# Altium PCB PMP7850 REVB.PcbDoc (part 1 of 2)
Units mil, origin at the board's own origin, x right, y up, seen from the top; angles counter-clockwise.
Board outline 4000 x 3000 mil, 4 copper layers (Top Layer, MidLayer1, MidLayer2, Bottom Layer), stack 61.2 mil thick; 106 components, 51 nets, 290 pads, 278 vias.
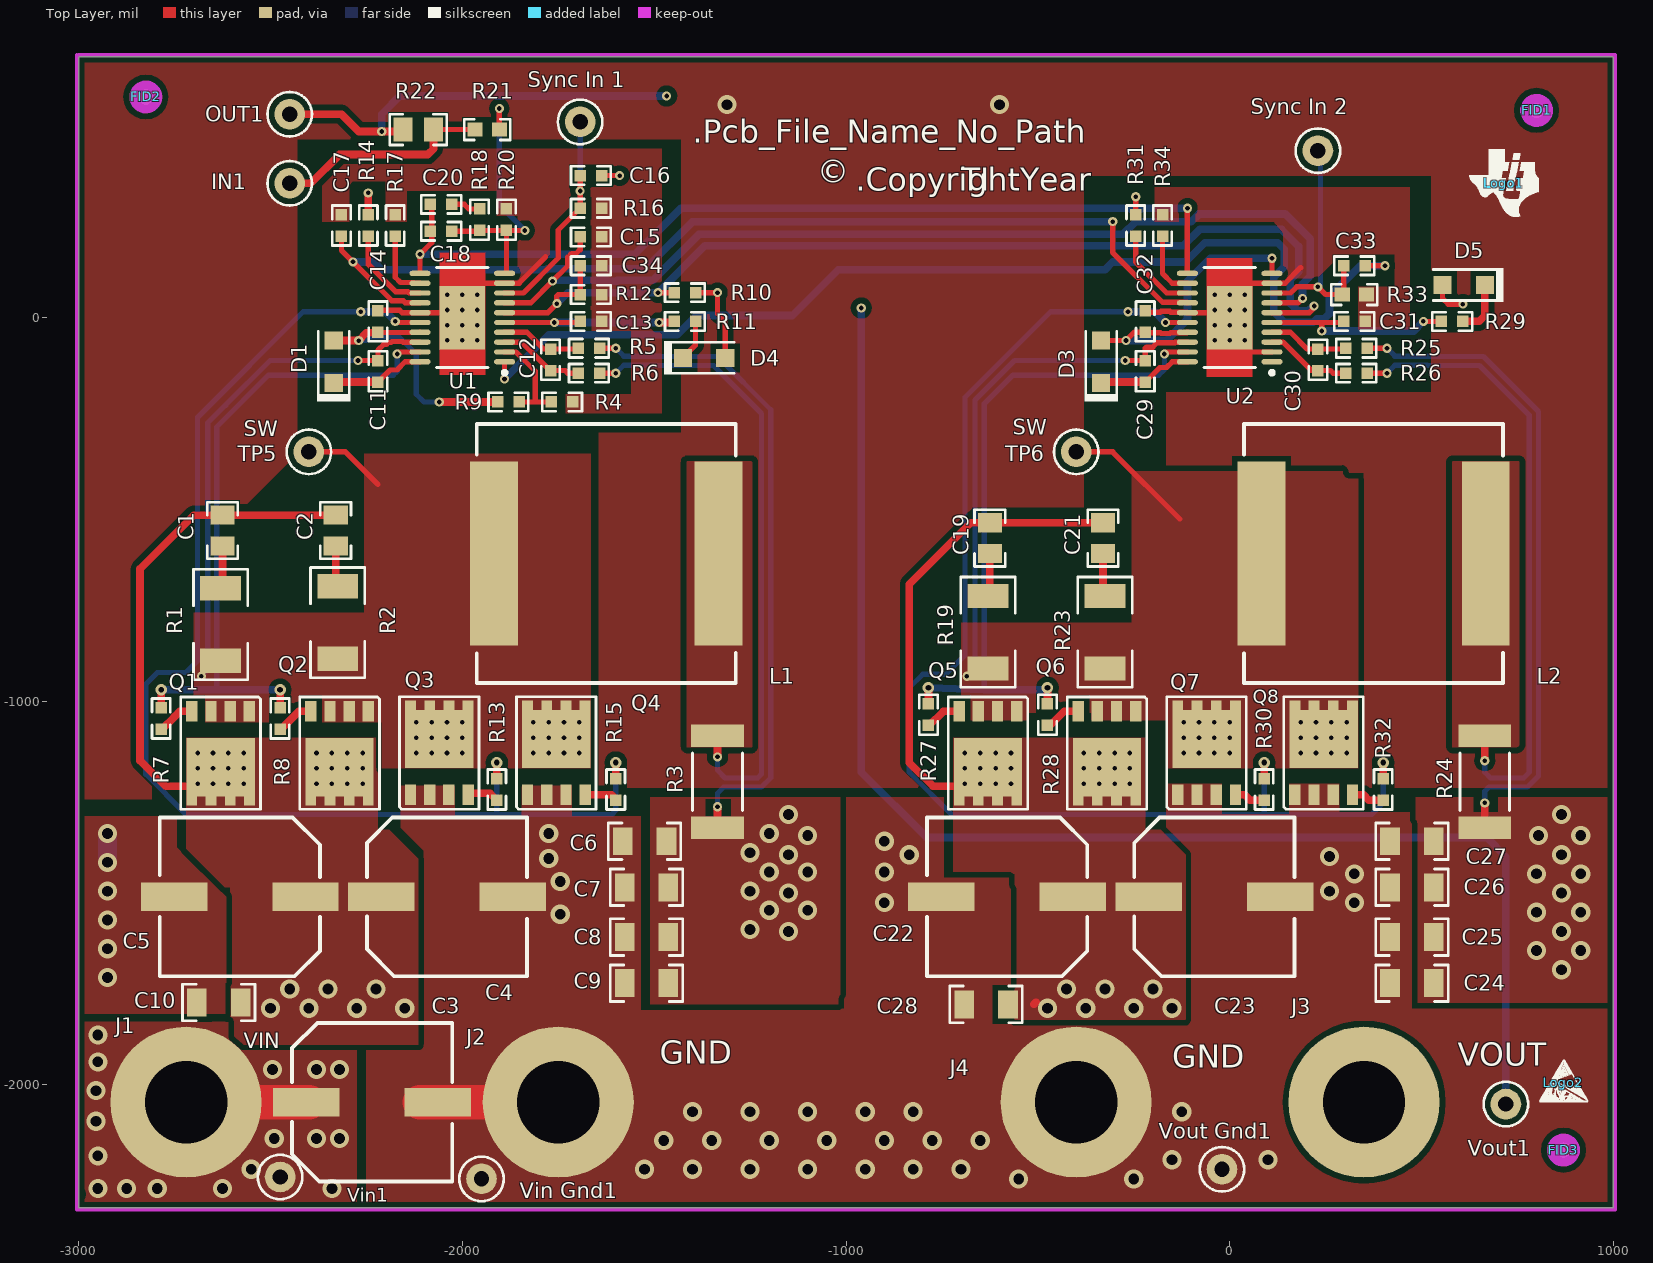
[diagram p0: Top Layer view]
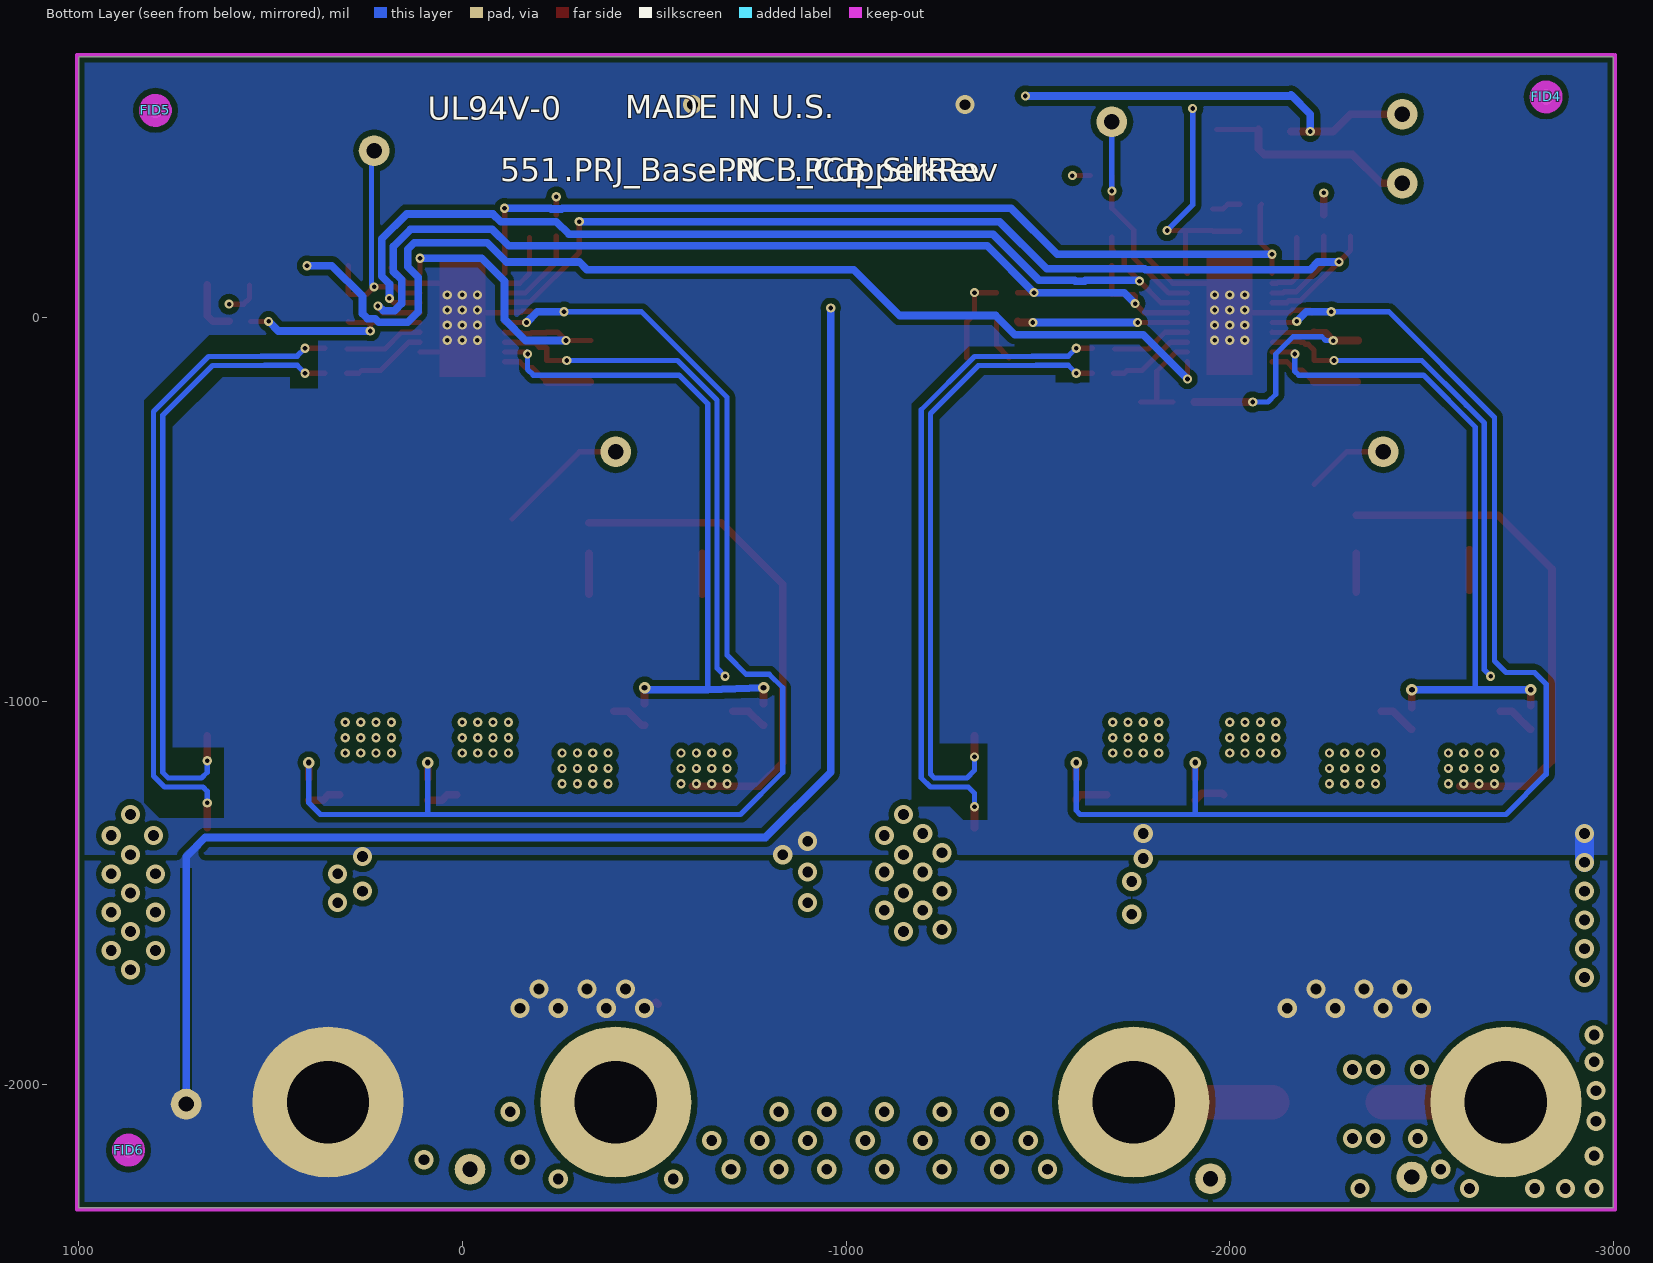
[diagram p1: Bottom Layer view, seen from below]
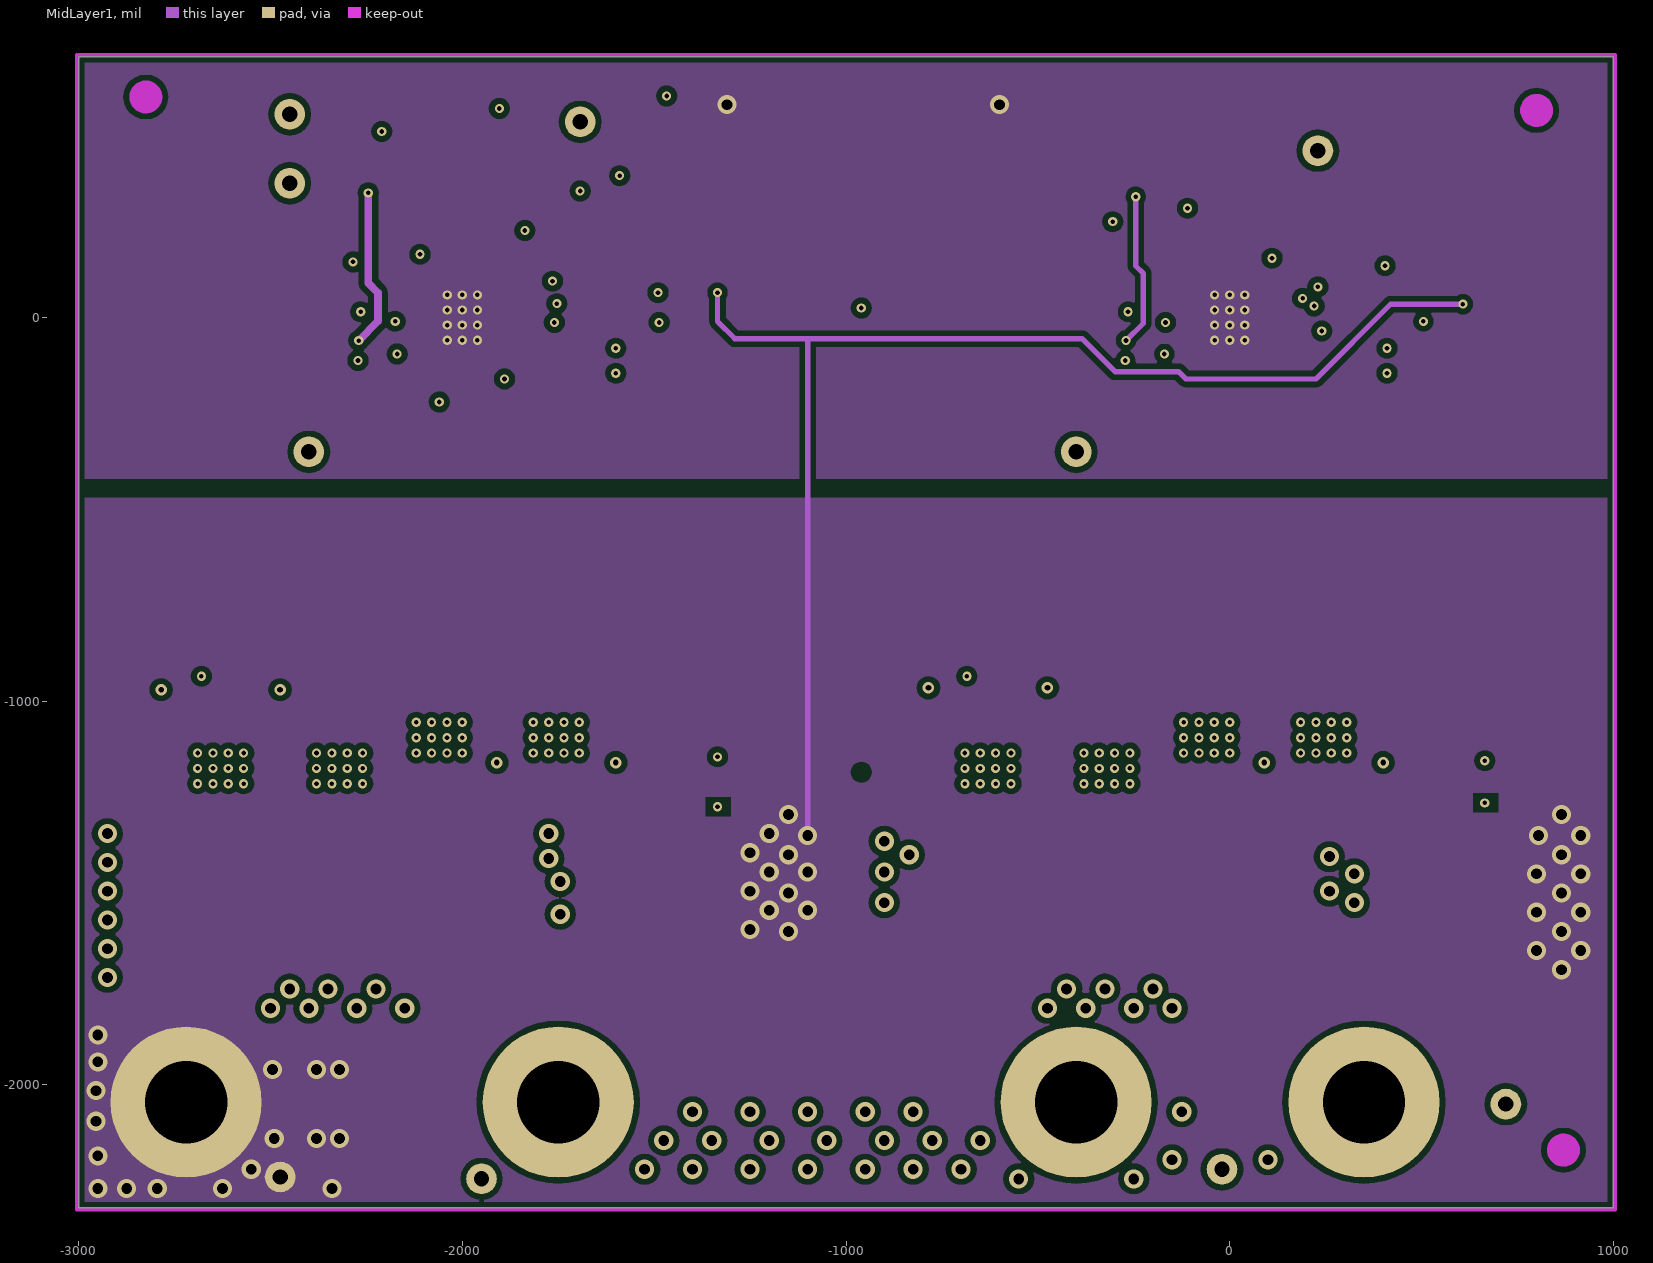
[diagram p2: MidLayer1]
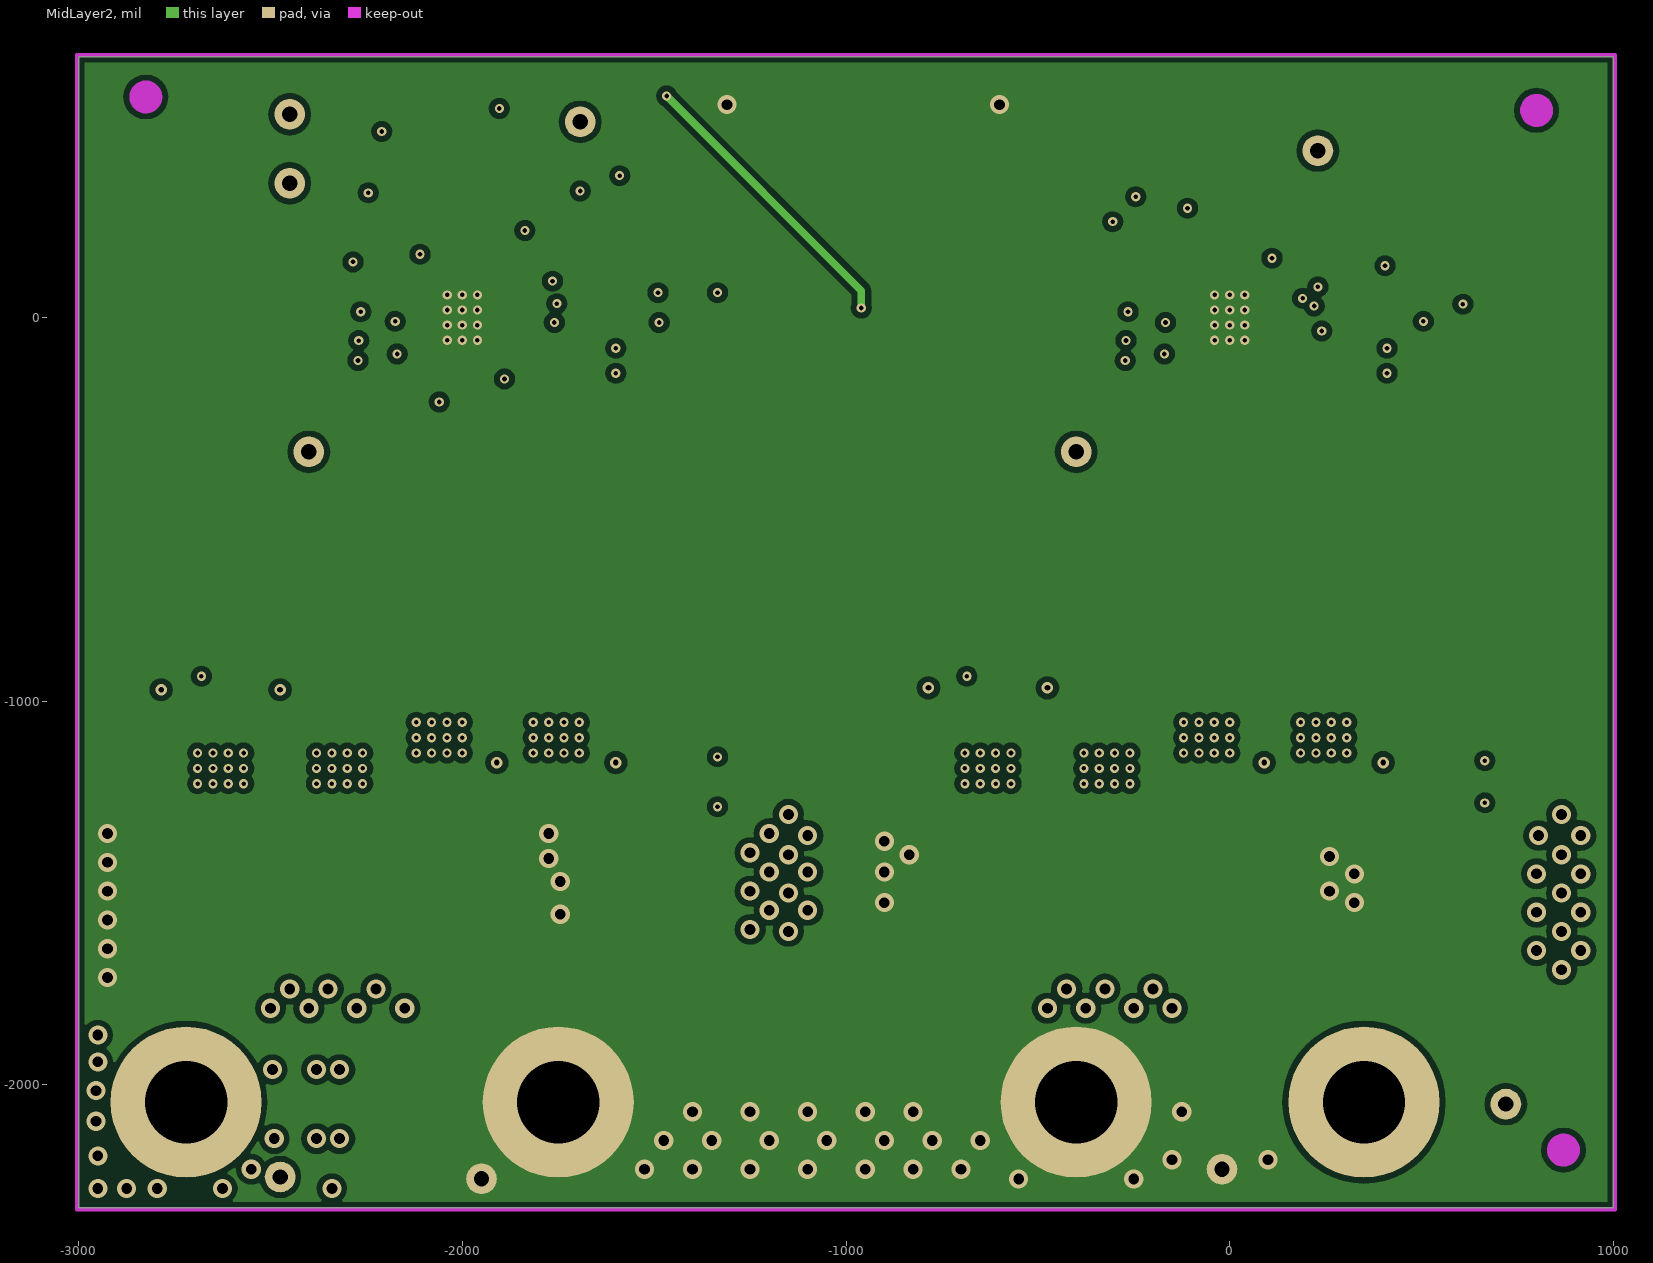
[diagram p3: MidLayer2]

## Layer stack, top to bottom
Top Solder: solder mask 0.4, Solder Resist, Dk 3.5
Top Layer: signal copper 1.4
Dielectric1: core 12.6, FR-4, Dk 4.8
MidLayer1: signal copper 0.7
Dielectric2: prepreg 31.8, FR-4, Dk 4.8
MidLayer2: signal copper 0.7
Dielectric3: core 12.6, FR-4, Dk 4.8
Bottom Layer: signal copper 1.4
Bottom Solder: solder mask 0.4, Solder Resist, Dk 3.5

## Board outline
-3000,-2320 -3000,680 1000,680 1000,-2320

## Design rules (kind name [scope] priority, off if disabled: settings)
AcuteAngle [All] p1: minimum=4.50000000000000E+0001 checktracksonly=FALSE
AssemblyTestPointUsage [All] p1: valid=2
Clearance Clearance_Polygons [IsRegion] p1: gap=15
Clearance Clearance_BoardEdge_MountingHoles [OnCopper and InComponentClass('Mounting Holes') vs IsKeepOut] p2: gap=40
Clearance Clearance_BoardEdge_Poly [OnCopper and InPoly vs IsKeepOut] p3: gap=25
Clearance Clearance_BoardEdge [OnCopper and Not InComponentClass('Logo') and not InComponentClass('FiducialMark') and not InRegion(1000,500,4000,800) vs IsKeepOut] p4: gap=75
Clearance Clearance_1 [All] p5: gap=10
ComponentClearance ComponentClearance_Logo [InComponentClass(Logo)] p1: gap=50 collisioncheckmode=3 verticalgap=10 showdistances=FALSE
ComponentClearance ComponentClearance_ScrewToNut [(HasFootprint('NY PMS 440 0025 PH')) vs (HasFootprint('Keystone_1902C'))] p2: gap=5 collisioncheckmode=3 verticalgap=10 showdistances=FALSE
ComponentClearance ComponentClearance_MountingHoles [InComponentClass('Mounting Holes')] p3: gap=250 collisioncheckmode=3 verticalgap=100000 showdistances=FALSE
ComponentClearance ComponentClearance_SmallPassives [HasFootprint('0201*') or HasFootprint('0402*') or HasFootprint('0508') or HasFootprint('0603*') or HasFootprint('0612') or HasFootprint('0805*') or HasFootprint('0815*') or HasFootprint('0830*') or HasFootprint('1206*') or HasFootprint('1210*') or HasFootprint('1808*') or HasFootprint('1812*') or HasFootprint('1825*') or HasFootprint('2010*') or HasFootprint('2220*') or HasFootprint('2225*') or HasFootprint('2512*') or HasFootprint('2728*') or HasFootprint('3518*') vs HasFootprint('0201*') or HasFootprint('0402*') or HasFootprint('0508') or HasFootprint('0603*') or HasFootprint('0612') or HasFootprint('0805*') or HasFootprint('0815*') or HasFootprint('0830*') or HasFootprint('1206*') or HasFootprint('1210*') or HasFootprint('1808*') or HasFootprint('1812*') or HasFootprint('1825*') or HasFootprint('2010*') or HasFootprint('2220*') or HasFootprint('2225*') or HasFootprint('2512*') or HasFootprint('2728*') or HasFootprint('3518*')] p4: gap=20 collisioncheckmode=3 verticalgap=10 showdistances=FALSE
ComponentClearance ComponentClearance_THtoSMT [IsThruComponent vs IsSMTComponent] p5: gap=100 collisioncheckmode=3 verticalgap=100000 showdistances=FALSE
ComponentClearance ComponentClearance_THtoTH [IsThruComponent vs IsThruComponent] p6: gap=118.11 collisioncheckmode=3 verticalgap=100000 showdistances=FALSE
ComponentClearance [All] p7: gap=40 collisioncheckmode=3 verticalgap=10 showdistances=FALSE
DiffPairsRouting [All] p1: maxlimit=100 minlimit=10 mostfreqgap=10 toplayer_minwidth=15 toplayer_maxwidth=15 toplayer_prefwidth=15 midlayer1_minwidth=15 midlayer1_maxwidth=15 midlayer1_prefwidth=15 midlayer2_minwidth=15 midlayer2_maxwidth=15 midlayer2_prefwidth=15 bottomlayer_minwidth=15 bottomlayer_maxwidth=15 bottomlayer_prefwidth=15 maxuncoupledlength=1000
FabricationTestPointUsage TestPointUsage [All] p1: valid=2 allowmultiple=FALSE
FabricationTestpoint Testpoint [All] p1: side=3 testpointundercomponent=TRUE minsize=40 maxsize=100 preferedsize=60 minholesize=0 maxholesize=40 preferedholesize=32 testpointgrid=1 allowsidetop=TRUE allowsidebottom=TRUE usegrid=TRUE gridtolerance=0.01
FanoutControl Fanout_LCC [IsLCC] p1: bgadir=Out bgaviamode=Centered fanoutstyle=Auto fanoutdirection=Alternating viagrid=1 // Fanout_LCC (Default Rule)
FanoutControl Fanout_BGA [IsBGA] p2: bgadir=Out bgaviamode=Centered fanoutstyle=Auto fanoutdirection=Alternating viagrid=1 // Fanout_BGA (Default Rule)
FanoutControl Fanout_Default [All] p4: bgadir=Out bgaviamode=Centered fanoutstyle=Auto fanoutdirection=Alternating viagrid=1 // Fanout_Default (Default Rule)
FanoutControl Fanout_Small [(CompPinCount < 5)] p5: bgadir=Out bgaviamode=Centered fanoutstyle=Auto fanoutdirection=OutThenIn viagrid=1 // Fanout_Small (Default Rule)
HoleSize [All] p1: absolutevalues=TRUE maxlimit=251 minlimit=8 maxpercent=80.000 minpercent=20.000
MinimumAnnularRing [All] p1: minimumring=6
MinimumSolderMaskSliver MinimumSolderMaskSliver_Logo [InComponentClass('Logo') vs InComponentClass('Logo')] p1: minsoldermaskwidth=0.7
MinimumSolderMaskSliver [All] p2: minsoldermaskwidth=4
PlaneConnect [All] p1: planeconnectstyle=Relief reliefexpansion=10 reliefentries=4 reliefconductorwidth=10 reliefairgap=10
PolygonConnect [All] p1: connectstyle=Direct reliefconductorwidth=10 reliefentries=4 polygonreliefangle="90 Angle" airgapwidth=10
RoomDefinition "PMP7850 2 phase design Rev 3 Schematic" [InComponentClass('PMP7850 2 phase design Rev 3 Schematic')] p1 off: confinementstyle=ConfineIn formatcopy=TRUE lockcomponents=FALSE outline -3692,-3854 -1692,-3854 -1692,-2854 -3692,-2854
RoutingVias [All] p1: holewidth=16 width=34 viastyle="Through Hole" minholewidth=8 minwidth=26 maxholewidth=40 maxwidth=65
SMDToCorner [All] p1: distance=30000
SilkToSilkClearance [All] p1: silktosilkclearance=5
SilkToSolderMaskClearance SilkscreenOverComponentPads [IsPad] p1: minsilkscreentomaskgap=5 clearancetoexposedcopper=TRUE
SolderMaskExpansion [All] p1: expansion=3
UnpouredPolygon [All] p1: allowunpoured=FALSE
Width [All] p1: maxlimit=100 minlimit=6 preferedwidth=10 checkconnectedcopper=TRUE
15 further rules are at their usual default settings.

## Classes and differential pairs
component class "PMP7850 2 phase design Rev 3 Schematic": C1 C2 C3 C4 C5 C6 C7 C8 C9 C10 C11 C12 C13 C14 C15 C16 C17 C18 C19 C20 C21 C22 C23 C24 C25 C26 C27 C28 C29 C30 C31 C32 C33 C34 D1 D3 D4 D5 IN1 J1 J2 J3 J4 L1 L2 OUT1 Q1 Q2 Q3 Q4 Q5 Q6 Q7 Q8 R1 R2 R3 R4 R5 R6 R7 R8 R9 R10 R11 R12 R13 R14 R15 R16 R17 R18 R19 R20 R21 R22 R23 R24 R25 R26 R27 R28 R29 R30 R31 R32 R33 R34 "Sync In 1" "Sync In 2" TP5 TP6 U1 U2 Vin1 "Vin Gnd1" Vout1 "Vout Gnd1"
component class FiducialMark: FID1 FID2 FID3 FID4 FID5 FID6
component class 870xxxxxx_Hardware_ANSI-B: FID1 FID2 FID3 FID4 FID5 FID6 Logo1 Logo2
component class Logo: Logo1
differential pair SW1: +SW1_P -SW1_N
differential pair SW2: +SW2_P -SW2_N

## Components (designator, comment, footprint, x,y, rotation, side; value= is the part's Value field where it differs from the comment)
C1 "GRM2165C2A471JA01D" 0805_HV -2625,-555 r270 top
C2 "GRM2165C2A471JA01D" 0805_HV -2330,-555 r270 top
C3 "10SVPS330M" SVPS_F8 -2235,-2045 r0 top
C4 "16SVP180MX" SVP_F8 -2040,-1510 r0 top
C5 "16SVP180MX" SVP_F8 -2580,-1510 r180 top
C6 "C3216X5R1C106M" 1206 -1525,-1365 r180 top
C7 "C3216X5R1C106M" 1206 -1520,-1485 r180 top
C8 "C3216X5R1C106M" 1206 -1520,-1615 r180 top
C9 "C3216X5R1C106M" 1206 -1520,-1735 r180 top
C10 "C3216X5R1C106M" 1206 -2635,-1785 r180 top
C11 "GRM188R71E474KA12D" 0603_HV -2220,-140 r270 top
C12 "GRM1885C1H101JA01D" 0603_HV -1770,-110 r90 top
C13 "GRM188R71E474KA12D" 0603_HV -1665,-10 r0 top
C14 "GRM188R71E105KA12D" 0603_HV -2220,-10 r90 top
C15 "GRM188R71E104KA01D" 0603_HV -1665,210 r0 top
C16 "GRM1885C1H101JA01D" 0603_HV -1665,370 r180 top
C17 "GRM188R71E473KA01D" 0603_HV -2315,240 r90 top
C18 "GRM1885C1H101JA01D" 0603_HV -2055,225 r180 top
C19 "GRM2165C2A471JA01D" 0805_HV -625,-575 r270 top
C20 "C0603C223K3RACTU" 0603_HV -2055,295 r180 top
C21 "GRM2165C2A471JA01D" 0805_HV -330,-575 r270 top
C22 "16SVP180MX" SVP_F8 -580,-1510 r180 top
C23 "16SVP180MX" SVP_F8 -40,-1510 r0 top
C24 "C3216X5R1C106M" 1206 475,-1735 r180 top
C25 "C3216X5R1C106M" 1206 475,-1615 r180 top
C26 "C3216X5R1C106M" 1206 475,-1485 r180 top
C27 "C3216X5R1C106M" 1206 475,-1365 r180 top
C28 "C3216X5R1C106M" 1206 -635,-1790 r180 top
C29 "GRM188R71E474KA12D" 0603_HV -220,-140 r270 top
C30 "GRM1885C1H101JA01D" 0603_HV 230,-110 r90 top
C31 "GRM188R71E474KA12D" 0603_HV 325,-10 r0 top
C32 "GRM188R71E105KA12D" 0603_HV -220,-10 r90 top
C33 "GRM1885C1H101JA01D" 0603_HV 325,135 r180 top
C34 "GRM188R71C103KA01D" 0603_HV -1665,135 r0 top
D1 "PMEG6010CEH,115" SOD-123F -2335,-115 r90 top
D3 "PMEG6010CEH,115" SOD-123F -335,-115 r90 top
D4 "PMEG6010CEH,115" SOD-123F -1370,-105 r0 top
D5 "PMEG6010CEH,115" SOD-123F 610,85 r180 top
FID1 "Fiducial" Fiducial10-20 800,540 r0 top
FID2 "Fiducial" Fiducial10-20 -2825,575 r0 top
FID3 "Fiducial" Fiducial10-20 870,-2170 r0 top
FID4 "Fiducial" Fiducial10-20 -2825,575 r270 bottom
FID5 "Fiducial" Fiducial10-20 800,540 r270 bottom
FID6 "Fiducial" Fiducial10-20 870,-2170 r270 bottom
IN1 "5002" Keystone5002 -2450,350 r0 top
J1 "575-4" Keystone_575-4 -2720,-2045 r0 top
J2 "575-4" Keystone_575-4 -1750,-2045 r0 top
J3 "575-4" Keystone_575-4 350,-2045 r0 top
J4 "575-4" Keystone_575-4 -400,-2045 r0 top
L1 "IHLP6767GZER3R3MA1" IHLP6767GZ -1625,-615 r180 top
L2 "IHLP6767GZER3R3MA1" IHLP6767GZ 375,-615 r180 top
Logo1 "Texas Instruments" TI_Symbol_Overlay_Small 715,350 r0 top
Logo2 "ESD Susceptible" ESD_Overlay_Small 870,-1995 r0 top
OUT1 "5002" Keystone5002 -2450,530 r0 top
Q1 "CSD16415Q5" "Q5A WITH VIAS" -2630,-1135 r270 top
Q2 "CSD16415Q5" "Q5A WITH VIAS" -2320,-1135 r270 top
Q3 "CSD16415Q5" "Q5A WITH VIAS" -2060,-1135 r90 top
Q4 "CSD16415Q5" "Q5A WITH VIAS" -1755,-1135 r90 top
Q5 "CSD16415Q5" "Q5A WITH VIAS" -630,-1135 r270 top
Q6 "CSD16415Q5" "Q5A WITH VIAS" -320,-1135 r270 top
Q7 "CSD16415Q5" "Q5A WITH VIAS" -60,-1135 r90 top
Q8 "CSD16415Q5" "Q5A WITH VIAS" 245,-1135 r90 top
R1 "ERJ-12ZYJ7R5U" 2010M -2630,-800 r270 top
R2 "ERJ-12ZYJ7R5U" 2010M -2325,-795 r270 top
R3 "ERJ-M1WTF1M5U" 2512M -1335,-1210 r90 top
R4 "ERJ-3GEY0R00V" 0603_HV -1740,-220 r180 top
R5 "CRCW0603100RFKEA" 0603_HV -1670,-80 r0 top
R6 "CRCW0603100RFKEA" 0603_HV -1670,-145 r0 top
R7 "ERJ-3GEY0R00V" 0603_HV -2785,-1045 r90 top
R8 "ERJ-3GEY0R00V" 0603_HV -2475,-1045 r90 top
R9 "CRCW0603158KFKEA" 0603_HV -1880,-220 r180 top
R10 "CRCW060349K9FKEA" 0603_HV -1420,65 r0 top
R11 "CRCW06033R30JNEA" 0603_HV -1420,-10 r0 top
R12 "RC0603FR-0715KL" 0603_HV -1665,60 r180 top
R13 "ERJ-3GEY0R00V" 0603_HV -1910,-1230 r90 top
R14 "ERJ-3GEY0R00V" 0603_HV -2245,240 r90 top
R15 "ERJ-3GEY0R00V" 0603_HV -1600,-1230 r90 top
R16 "CRCW060320K0FKEA" 0603_HV -1665,285 r180 top
R17 "RC0603FR-0739KL" 0603_HV -2175,240 r270 top
R18 "CRCW060315K0FKEA" 0603_HV -1955,255 r90 top
R19 "ERJ-12ZYJ7R5U" 2010M -630,-820 r270 top
R20 "CRCW06032K67FKEA" 0603_HV -1885,255 r90 top
R21 "CRCW060323K2FKEA" 0603 -1935,490 r180 top
R22 "CRCW0805604RFKEA" 0805_HV -2115,490 r0 top
R23 "ERJ-12ZYJ7R5U" 2010M -325,-820 r270 top
R24 "ERJ-M1WTF1M5U" 2512M 665,-1210 r90 top
R25 "CRCW0603100RFKEA" 0603_HV 330,-80 r0 top
R26 "CRCW0603100RFKEA" 0603_HV 330,-145 r0 top
R27 "ERJ-3GEY0R00V" 0603_HV -785,-1035 r90 top
R28 "ERJ-3GEY0R00V" 0603_HV -475,-1035 r90 top
R29 "CRCW06033R30JNEA" 0603_HV 580,-10 r0 top
R30 "ERJ-3GEY0R00V" 0603_HV 90,-1230 r90 top
R31 "ERJ-3GEY0R00V" 0603_HV -245,240 r90 top
R32 "ERJ-3GEY0R00V" 0603_HV 400,-1230 r90 top
R33 "CRCW060320K0FKEA" 0603 325,60 r180 top
R34 "RC0603FR-0739KL" 0603_HV -175,240 r270 top
"Sync In 1" "5002" Keystone5002 -1693,510 r0 top
"Sync In 2" "5002" Keystone5002 230,435 r90 top
TP5 "5002" Keystone5002 -2400,-350 r0 top
TP6 "5002" Keystone5002 -400,-350 r0 top
U1 "LM5122MH" "MXA20A_L - 10milVia" -2000,0 r180 top
U2 "LM5122MH" "MXA20A_L - 10milVia" 0,0 r180 top
Vin1 "5000" Keystone5000 -2475,-2240 r0 top
"Vin Gnd1" "5001" Keystone5001 -1950,-2245 r90 top
Vout1 "5000" Keystone5000 720,-2050 r90 top
"Vout Gnd1" "5001" Keystone5001 -20,-2220 r90 top

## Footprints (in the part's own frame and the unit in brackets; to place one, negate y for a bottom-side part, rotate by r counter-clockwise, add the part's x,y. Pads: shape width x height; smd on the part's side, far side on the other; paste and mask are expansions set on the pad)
0603 [mm] "0603 from SM-752 data"
  rect 1x0.95 smd: 1(-0.8,0) 2(0.8,0)
  silkscreen extent -1.52,-0.69 1.52,0.69, body extent -0.87,-0.47 0.87,0.47, height 0.85
0603_HV [mil] "Ernesto recommended land pattern.  26 mil between pads."
  rect 30x30 smd: 1(-28,0) 2(28,0)
  silkscreen extent -52,-24 52,24, body extent -34,-19 34,19, height 33
0805_HV [mil] "0805 with 30mil clearance between pads"
  rect 50x63 smd: 1(-40,0) 2(40,0)
  silkscreen extent -74,-40 74,40, body extent -43,-29 43,29, height 43
1206 [mm] "1206 from SM-752 data"
  rect 1.3x1.85 smd: 1(-1.45,0) 2(1.45,0)
  silkscreen extent -2.4,-1.21 2.4,1.21, body extent -1.7,-0.9 1.7,0.9, height 1.35
2010M [mm]
  rect 1.6x2.7 smd: 1(-2.4,0) 2(2.4,0)
  silkscreen extent -3.65,-1.8 3.65,1.8, body extent -2.73,-1.45 2.73,1.45, height 1.66
2512M [mm] "Chip Resistor, Body 6.3x3.2mm, IPC Low Density"
  rect 1.5x3.5 smd: 1(-3.05,0) 2(3.05,0)
  silkscreen extent -1.9,-1.65 1.9,1.65, body extent -3.22,-1.67 3.22,1.67, height 0.71
ESD_Overlay_Small [mil]
  silkscreen extent -62,-48 64,61
Fiducial10-20 [mm]
  round 1 smd paste-0.5 mask+0.5: 1(0,0)
  Keep-Out Layer circle w1.178: c0,0 r0.5
IHLP6767GZ [mm] "IHLP6767GZ VISHAY DALE INDUCTOR"
  rect 3.175x12.19 smd: 1(-7.428,0) 2(7.428,0)
  silkscreen extent -8.57,-8.57 8.57,8.57, body extent -8.62,-8.6 8.67,8.67, height 7
Keystone5000 [mil] "For Keystone 500x miniature loop terminals"
  round 80 hole 40: 1(0,0)
  silkscreen extent -58,-58 58,58, body extent -49,-49 49,49, height 182
Keystone5001 [mil] "For Keystone 500x miniature loop terminals"
  round 80 hole 40: 1(0,0)
  silkscreen extent -58,-58 58,58, body extent -49,-49 49,49, height 182
Keystone5002 [mil] "For Keystone 500x miniature loop terminals"
  round 80 hole 40: 1(0,0)
  silkscreen extent -58,-58 58,58, body extent -49,-49 49,49, height 182
Keystone_575-4 [mm] "Banana Jack"
  round 10 hole 5.45: 1(0,0)
  body extent -3.95,-3.95 3.92,3.93, height 2.36
"MXA20A_L - 10milVia" [mm] "TSOP, 20-Leads, Body 6.5x4.4mm, Pitch 0.65mm, Exposed Pad, IPC High Density"
  oval 1.4x0.35 smd: 1(-2.8,2.925) 2(-2.8,2.275) 3(-2.8,1.625) 4(-2.8,0.975) 5(-2.8,0.325) 6(-2.8,-0.325) 7(-2.8,-0.975) 8(-2.8,-1.625) 9(-2.8,-2.275) 10(-2.8,-2.925) 11(2.8,-2.925) 12(2.8,-2.275) 13(2.8,-1.625) 14(2.8,-0.975) 15(2.8,-0.325) 16(2.8,0.325) 17(2.8,0.975) 18(2.8,1.625) 19(2.8,2.275) 20(2.8,2.925)
  rect 3x4.2 smd: 21(0,0)
  silkscreen extent -2.93,-3.3 1.7,3.77, body extent -2.25,-3.3 2.25,3.3, height 1.1
"Q5A WITH VIAS" [mm] "TI 15A WITH VIAS"
  round 0.3 on Top Overlay: 0(-2.766,3.087)
  rect 1.372x0.75 smd paste-0.1 mask+0.051: 1(-2.77,1.905) 2(-2.77,0.635) 3(-2.77,-0.635) 4(-2.77,-1.905)
  rect 0.675x0.71 smd paste-0.1 mask+0.051: 5(3.134,-1.905) 6(3.134,-0.635) 7(3.134,0.635) 8(3.134,1.905)
  rect 3.85x4.52 smd paste-2.2 mask+0.051: 9(0.939,0)
  silkscreen extent -3.71,-2.63 3.72,2.64, body extent -3.05,-2.5 3.05,2.5, height 1.11
SOD-123F [mm] "NXP recommended land pattern"
  rect 1.2x1.2 smd paste-0.05: 1(-1.4,0) 2(1.4,0)
  silkscreen extent -2.64,-1.12 2.01,1.12, body extent -1.8,-0.85 1.8,0.85, height 1.2
SVP_F8 [mm] "SANYO SVP_F8"
  rect 4.4x1.9 smd: 1(-4.35,0) 2(4.35,0)
  silkscreen extent -5.3,-5.25 5.3,5.25, body extent -5.25,-5.23 5.33,5.2, height 8
SVPS_F8 [mm] "SANYO SVPS_F8"
  rect 4.4x1.9 smd: 1(-4.35,0) 2(4.35,0)
  silkscreen extent -5.3,-5.25 5.3,5.25, body extent -5.25,-5.23 5.33,5.2, height 8
TI_Symbol_Overlay_Small [mil]
  silkscreen extent -90,-88 91,88

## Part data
C1 C2 C19 C21: "CAP, CERM, 470pF, 100V, +/-5%, C0G/NP0, 0805"
C3: "CAP, AL, 330uF, 10V, +/-20%, SMD"
C4 C5 C22 C23: "CAP, AL, 180uF, 16V, +/-20%, SMD"
C6 C7 C8 C9 C10 C24 C25 C26 C27 C28: "CAP, CERM, 10uF, 16V, +/-20%, X5R, 1206"
C11 C13 C29 C31: "CAP, CERM, 0.47uF, 25V, +/-10%, X7R, 0603"
C12 C16 C18 C30 C33: "CAP, CERM, 100pF, 50V, +/-5%, C0G/NP0, 0603"
C14 C32: "CAP, CERM, 1uF, 25V, +/-10%, X7R, 0603"
C15: "CAP, CERM, 0.1uF, 25V, +/-10%, X7R, 0603"
C17: "CAP, CERM, 0.047uF, 25V, +/-10%, X7R, 0603"
C20: "CAP, CERM, 0.022uF, 25V, +/-10%, X7R, 0603"
C34: "CAP, CERM, 0.01uF, 16V, +/-10%, X7R, 0603"
D1 D3 D4 D5: "Diode, Schottky, 60V, 1A, SOD-123F"
FID1 FID2 FID3 FID4 FID5 FID6: "Fiducial mark.  There is nothing to buy or mount."
IN1 OUT1 "Sync In 1" "Sync In 2" TP5 TP6: "Test Point, TH, Miniature, White"
J1 J2 J3 J4: "Standard Banana Jack, Uninsulated, 5.5mm"
L1 L2: "INDUCTOR POWER 3.3UH 54A SMD"
Logo1: library part TI_Logo, "Texas Instrument Corporate Signature"
Logo2: library part ESD_Susceptible, "ESD Susceptible Symbol"
Q1 Q2 Q3 Q4 Q5 Q6 Q7 Q8: "MOSFET N-CH 25V 8SON"
R1 R2 R19 R23: "RESISTOR 7.5 OHM 3/4W 5% 2010"
R3 R24: "RES, 0.0015 ohm, 1%, 1W, 2512"
R4 R7 R8 R13 R14 R15 R27 R28 R30 R31 R32: "RES, 0 ohm, 5%, 0.1W, 0603"
R5 R6 R25 R26: "RES, 100 ohm, 1%, 0.1W, 0603"
R9: "RES, 158k ohm, 1%, 0.1W, 0603"
R10: "RES, 49.9k ohm, 1%, 0.1W, 0603"
R11 R29: "RES, 3.3 ohm, 5%, 0.1W, 0603"
R12 R18: "RES, 15.0k ohm, 1%, 0.1W, 0603"
R16 R33: "RES, 20.0k ohm, 1%, 0.1W, 0603"
R17 R34: "RES, 39.0k ohm, 1%, 0.1W, 0603"
R20: "RES, 2.67k ohm, 1%, 0.1W, 0603"
R21: "RES, 23.2k ohm, 1%, 0.1W, 0603"
R22: "RES, 604 ohm, 1%, 0.125W, 0805"
U1 U2: library part LM5122
Vin1 Vout1: "Test Point, TH, Miniature, Red"
"Vin Gnd1" "Vout Gnd1": "Test Point, TH, Miniature, Black"

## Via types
v1: diameter 24, hole 12, Top Layer to Bottom Layer, 169 vias
v2: diameter 50, hole 28, Top Layer to Bottom Layer, 101 vias
v3: diameter 30, hole 15, Top Layer to Bottom Layer, 8 vias

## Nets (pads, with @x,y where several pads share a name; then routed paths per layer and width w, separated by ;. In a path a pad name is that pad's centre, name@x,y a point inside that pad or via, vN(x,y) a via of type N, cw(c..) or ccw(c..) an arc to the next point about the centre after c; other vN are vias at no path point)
BST1: C11.2 D1.1 U1.20 | length 244.5
  Top Layer w13.78: C11.2@-2220,-168 -2188.5,-136.5 -2170.64,-136.5 -2149.3,-115.16 U1.20@-2110.24,-115.16
  Top Layer w20: D1.1@-2332.88,-168 C11.2@-2220,-168
BST2: C29.2 D3.1 U2.20 | length 244.5
  Top Layer w13.78: C29.2@-220,-168 -182,-130 -164.14,-130 -149.3,-115.16 U2.20@-110.24,-115.16
  Top Layer w20: D3.1@-332.88,-168 C29.2@-220,-168
COMP: C18.2 C20.2 U1.11 U2.11 | length 2415.2
  Top Layer w13.78: U1.11@-2110.24,115.16 v1(-2110.24,164.76) -2080,195 -2080,292 C20.2@-2083,295 ; U2.11@-110.24,115.16 -110.24,284.76 v1(-110,285)
  Bottom Layer w20: v1(-2110.24,164.76) -1550.24,164.76 -1430,285 -260.25,285 -258.25,283 -231.75,283 -229.75,285 v1(-110,285)
CSN1: C12.1 R6.1 U1.3 | length 225.3
  Top Layer w13.78: U1.3@-1889.76,-63.98 -1846.02,-63.98 -1772,-138 C12.1@-1770,-138 -1732,-138 -1725,-145 R6.1@-1698,-145
CSN1_N: L1.1 R3.2 R6.2 | length 1640.1
  Top Layer w13.78: R6.2@-1642,-145 v1(-1600,-145)
  Top Layer w20: v1(-1335,-1145) R3.2@-1335,-1089.92
  Bottom Layer w13.78: v1(-1600,-145) -1579.39,-124.39 -1495,-124.39 -1494.39,-125 -1345,-125 -1220,-250 -1220,-1190 -1230,-1200 -1315,-1200 -1335,-1180 v1(-1335,-1145)
CSN2: C30.1 R26.1 U2.3 | length 225.3
  Top Layer w13.78: U2.3@110.24,-63.98 138.98,-63.98 213,-138 C30.1@230,-138 263,-138 270,-145 R26.1@302,-145
CSN2_N: L2.1 R24.2 R26.2 | length 1639.8
  Top Layer w13.78: R26.2@358,-145 v1(410,-145)
  Top Layer w20: v1(665,-1155) R24.2@665,-1089.92
  Bottom Layer w13.78: v1(410,-145) 430.61,-124.39 515,-124.39 515.61,-125 651.37,-125 781.22,-254.85 781.22,-1185.15 766.37,-1200 680,-1200 665,-1185 v1(665,-1155)
CSP1: C12.2 R5.1 U1.4 | length 207.8
  Top Layer w13.78: U1.4@-1889.76,-38.39 -1831.61,-38.39 -1788,-82 C12.2@-1770,-82 R5.1@-1700,-82
CSP2: C30.2 R25.1 U2.4 | length 207.8
  Top Layer w13.78: U2.4@110.24,-38.39 158.39,-38.39 202,-82 C30.2@230,-82 R25.1@300,-82
FSYNC: C16.1 | length 47
  Top Layer w13.78: C16.1@-1637,370 v1(-1590,370)
GND: "Vin Gnd1.1" "Vout Gnd1.1" C3.2 C4.2 C5.2 C6.2 C7.2 C8.2 C9.2 C10.2 C13.2 C14.2 C15.2 C17.2 C22.2 C23.2 C24.2 C25.2 C26.2 C27.2 C28.2 C31.2 C32.2 C34.2 J2.1 J4.1 Q3.1 Q3.2 Q3.3 Q4.1 Q4.2 Q4.3 Q7.1 Q7.2 Q7.3 Q8.1 Q8.2 Q8.3 R4.1 R12.1 R16.1 R17.1 R20.2 R33.1 R34.1 U1.9 U1.15 U1.21 U2.2 U2.9 U2.15 U2.21 | length 1328.8
  Top Layer w13.78: C14.2@-2214.8,12.8 -2208.7,18.89 -2163.03,18.89 -2156.94,12.8 U1.15@-2110.24,12.8 U1.21@-2012.8,12.8 ; -1970,85 -1965.43,89.57 U1.9@-1889.76,89.57 -1852,89.57 -1783.28,158.28 ; C32.2@-220,18 -216.09,14.09 -181.17,14.09 -179.17,16.09 -155.24,16.09 -153.24,14.09 -111.54,14.09 U2.15@-110.24,12.8 U2.21@-12.8,12.8 ; 20,-90 20.43,-89.57 U2.2@110.24,-89.57 ; 35,90 35.43,89.57 U2.9@110.24,89.57 144.57,89.57 185,130
  Top Layer w90: C3.2@-2111.3,-2045 J2.1@-1750,-2045
  Bottom Layer w50: v2(-2925,-1420) v2(-2925,-1345)
  other v1: -2039.37,-59.06 -2000,-59.06 -1960.63,-59.06 -39.37,-59.06 0,-59.06 39.37,-59.06 -2039.37,-19.69 -2000,-19.69 -1960.63,-19.69 -39.37,-19.69 0,-19.69 39.37,-19.69 -2039.37,19.68 -2000,19.68 -1960.63,19.68 -39.37,19.68 0,19.68 39.37,19.68 -2039.37,59.06 -2000,59.06 -1960.63,59.06 -39.37,59.06 0,59.06 39.37,59.06
  other v2: -550,-2245 -250,-2245 -1525,-2220 -1400,-2220 -1250,-2220 -1100,-2220 -950,-2220 -825,-2220 -700,-2220 -150,-2195 100,-2195 -1475,-2145 -1350,-2145 -1200,-2145 -1050,-2145 -900,-2145 -775,-2145 -650,-2145 -1400,-2070 -1250,-2070 -1100,-2070 -950,-2070 -825,-2070 -125,-2070 -2925,-1720 -2925,-1645 -2925,-1570 -1745,-1555 -900,-1525 325,-1525 -2925,-1495 260,-1495 -1745,-1470 325,-1450 -900,-1445 -1775,-1410 260,-1405 -835,-1400 -900,-1365 -1775,-1345 -1310,555 -600,555
LO1: R13.2 R15.2 U1.16 | length 3351.7
  Top Layer w13.78: v1(-2175,-10) -2172.2,-12.8 U1.16@-2110.24,-12.8
  Top Layer w20: R13.2@-1910,-1202 v3(-1910,-1160) ; R15.2@-1600,-1202 v3(-1600,-1160)
  Bottom Layer w13.78: v1(-2265,15) -2415,15 -2690,-260 -2690,-895 -2720,-925 -2795,-925 -2825,-955 -2825,-1190 -2720,-1295 -1610,-1295 -1600,-1285 v3(-1600,-1160) ; -1910,-1295 v3(-1910,-1160)
  Bottom Layer w20: v1(-2265,15) -2200,15 v1(-2175,-10)
LO2: R30.2 R32.2 U2.16 | length 3373
  Top Layer w13.78: v1(-167.2,-12.8) U2.16@-110.24,-12.8
  Top Layer w20: R30.2@90,-1202 v3(90,-1160) ; R32.2@400,-1202 v3(400,-1160)
  Bottom Layer w13.78: v1(-265,15) -467.26,15 -690,-207.74 -690,-880 -740,-930 -800,-930 -835,-965 -835,-1185 -725,-1295 90,-1295 ; v3(90,-1160) 90,-1295 ; v3(400,-1160) 400,-1265 370,-1295 90,-1295
  Bottom Layer w20: v1(-265,15) -195,15 v1(-167.2,-12.8)
MODE1: R14.1 U1.13 | length 239.1
  Top Layer w13.78: R14.1@-2245,212 -2245,138.63 -2173.97,67.6 -2142.57,67.6 -2138.94,63.98 U1.13@-2110.24,63.98
MODE2: R31.1 U2.13 | length 235.3
  Top Layer w13.78: R31.1@-245,212 -245,145 -163.98,63.98 U2.13@-110.24,63.98
NetC1_2: C1.2 R1.1 | length 105.5
  Top Layer w20: R1.1@-2625,-710.51 C1.2@-2625,-605
NetC2_2: C2.2 R2.1 | length 100.5
  Top Layer w20: R2.1@-2330,-715.51 C2.2@-2330,-615
NetC18_1: C18.1 R18.1 R20.1 R21.1 U1.10 | length 705.2
  Top Layer w13.78: C18.1@-2027,225 -1957,225 R18.1@-1955,227 R20.1@-1885,227 ; R21.1@-1903.5,490 v1(-1903.5,545) ; U1.10@-1889.76,115.16 -1885,119.92 R20.1@-1885,227 ; v1(-1837,227) R20.1@-1885,227
  Bottom Layer w13.78: v1(-1903.5,545) -1903.5,293.5 v1(-1837,227)
NetC19_2: C19.2 R19.1 | length 105.5
  Top Layer w20: R19.1@-625,-720.51 C19.2@-625,-615
NetC20_1: C20.1 R18.2 | length 77
  Top Layer w13.78: C20.1@-2027,295 -1995,295 -1983,283 R18.2@-1955,283
NetC21_2: C21.2 R23.1 | length 105.5
  Top Layer w20: R23.1@-330,-720.51 C21.2@-330,-615
NetC32_1: C32.1 D3.2 R31.2 U2.10 U2.17 | length 1250.6
  Top Layer w13.78: D3.2@-335,-59.88 v1(-270.12,-59.88) -269.88,-59.88 -248,-38 C32.1@-220,-38 ; R31.2@-245,268 v1(-245,315) ; C32.1@-218.31,-39.69 -181.17,-39.69 -179.17,-41.69 -155.24,-41.69 -153.24,-39.69 -111.54,-39.69 U2.17@-110.24,-38.39 ; U2.10@110.24,115.16 v1(110.24,154.76)
  MidLayer1 w13.78: v1(-270.12,-59.88) -225,-14.76 -225,115 -245,135 v1(-245,315)
  Bottom Layer w20: v1(-270.12,-59.88) -164.88,-59.88 -110,-5 -110,95 -50.24,154.76 v1(110.24,154.76)
NetD4_1: D4.1 R11.2 | length 108.7
  Top Layer w13.78: D4.1@-1425.12,-105 -1392,-71.88 R11.2@-1392,-10
NetD5_1: D5.1 R29.2 | length 143.3
  Top Layer w20: R29.2@608,-10 650,-10 665.12,5.12 D5.1@665.12,85
NetIN1_1: IN1.1 R21.2 R22.2 | length 570.8
  Top Layer w13.78: R22.2@-2075,490 R21.2@-1966.5,490
  Top Layer w20: IN1.1@-2450,350 -2395,350 -2320,425 -2090,425 -2075,440 R22.2@-2075,490
NetQ1_4: Q1.4 R7.1 | length 99.7
  Top Layer w20: R7.1@-2785,-1073 -2782.72,-1073 -2750,-1040.28 -2750,-1040 -2735.94,-1025.94 Q1.4@-2705,-1025.94
NetQ2_4: Q2.4 R8.1 | length 99.5
  Top Layer w20: R8.1@-2475,-1073 -2472.72,-1073 -2425.66,-1025.94 Q2.4@-2395,-1025.94
NetQ3_4: Q3.4 R13.1 | length 84.1
  Top Layer w20: Q3.4@-1985,-1244.06 -1980.94,-1240 -1928,-1240 R13.1@-1910,-1258
NetQ4_4: Q4.4 R15.1 | length 87.5
  Top Layer w20: Q4.4@-1680,-1244.06 -1610.94,-1244.06 -1600,-1255 R15.1@-1600,-1258
NetQ5_4: Q5.4 R27.1 | length 95.3
  Top Layer w20: R27.1@-785,-1063 -782.72,-1063 -745.66,-1025.94 Q5.4@-705,-1025.94
NetQ6_4: Q6.4 R28.1 | length 95.3
  Top Layer w20: R28.1@-475,-1063 -468,-1063 -430.94,-1025.94 Q6.4@-395,-1025.94
NetQ7_4: Q7.4 R30.1 | length 80.8
  Top Layer w20: Q7.4@15,-1244.06 39.06,-1244.06 53,-1258 R30.1@90,-1258
NetQ8_4: Q8.4 R32.1 | length 85.8
  Top Layer w20: Q8.4@320,-1244.06 349.06,-1244.06 363,-1258 R32.1@400,-1258
NetR4_2: R4.2 R9.1 U1.2 | length 264.7
  Top Layer w13.78: U1.2@-1889.76,-89.57 -1860.43,-89.57 -1810,-140 -1810,-220 ; R9.1@-1852,-220 -1810,-220 ; R4.2@-1768,-220 -1810,-220
RES: C17.1 U1.14 U2.14 | length 2667.7
  Top Layer w13.78: C17.1@-2315,212 -2315,175 v1(-2285,145) -2183.82,43.82 -2154.33,43.82 -2148.9,38.39 U1.14@-2110.24,38.39 ; v1(-305,250) -305,170 -174.87,39.87 -111.73,39.87 U2.14@-110.24,38.39
  Bottom Layer w20: v1(-2285,145) -2230,145 -2210,125 -1780.25,125 -1778.25,127 -1523,127 -1400,250 v1(-305,250)
SLOPE1: R17.2 U1.12 | length 174.7
  Top Layer w13.78: R17.2@-2175,208.5 -2175,105 -2161.38,91.38 -2124.63,91.38 -2122.82,89.57 U1.12@-2110.24,89.57
SLOPE2: R34.2 U2.12 | length 168.8
  Top Layer w13.78: R34.2@-175,208.5 -175,115 -149.57,89.57 U2.12@-110.24,89.57
SS: C15.1 U1.7 U2.7 | length 2623.9
  Top Layer w13.78: U1.7@-1889.76,38.39 -1821.61,38.39 v1(-1765,95) -1724.89,135.11 -1724.89,157 -1715,166.89 -1703.11,166.89 -1693,177 C15.1@-1693,210 ; U2.7@110.24,38.39 178.39,38.39 v1(190,50)
  Bottom Layer w20: v1(-1765,95) -1763,97 -1624.43,97 -1622.43,95 -1597.57,95 -1595.57,97 -1503,97 -1383.24,216.76 -278.24,216.76 -245,250 -99.75,250 -79.75,270 145,270 210,205 210,107.57 190,87.57 v1(190,50)
SW1_N: R7.2 R8.2 U1.19 | length 1732.6
  Top Layer w13.78: v1(-2170,-95) -2170,-90 -2169.57,-89.57 U1.19@-2110.24,-89.57
  Top Layer w20: R7.2@-2785,-1011.51 v3@-2785,-969.51 ; R8.2@-2475,-1017 v3(-2475,-970)
  Bottom Layer w13.78: -2640,-970 -2640,-285 -2505,-150 -2180,-150 -2170.43,-140.43 -2169.57,-140.43 -2169.57,-89.57 -2170,-90 v1(-2170,-95)
  Bottom Layer w20: v3(-2785,-970) -2640,-970 ; -2636.89,-970 v3(-2475,-970)
SW1_P: C11.1 L1.2 Q1.1 Q1.2 Q1.3 Q2.1 Q2.2 Q2.3 Q3.5 Q3.6 Q3.7 Q3.8 Q3.9 Q4.5 Q4.6 Q4.7 Q4.8 Q4.9 R1.2 R2.2 TP5.1 U1.18 | length 1538.4
  Top Layer w13.78: TP5.1@-2400,-350 -2305,-350 -2220,-435 ; v1(-2272,-112) C11.1@-2220,-112 -2220,-85 -2204.89,-69.89 -2198,-69.89 -2193.11,-65 -2185.86,-65 -2183.53,-62.67 -2155.61,-62.67 -2154.3,-63.98 U1.18@-2111.54,-63.98
  Bottom Layer w13.78: v1(-2680,-935) -2663.78,-918.78 -2663.78,-275.15 -2616.82,-228.19 -2500.63,-112 v1(-2272,-112)
  other v1: -2120,-1135 -2080,-1135 -2040,-1135 -2000,-1135 -1815,-1135 -1775,-1135 -1735,-1135 -1695,-1135 -2120,-1095 -2080,-1095 -2040,-1095 -2000,-1095 -1815,-1095 -1775,-1095 -1735,-1095 -1695,-1095 -2120,-1055 -2080,-1055 -2040,-1055 -2000,-1055 -1815,-1055 -1775,-1055 -1735,-1055 -1695,-1055
SW2_N: R27.2 R28.2 U2.19 | length 1756.9
  Top Layer w13.78: v1(-170,-95) -170,-90 -169.57,-89.57 U2.19@-110.24,-89.57
  Top Layer w20: R27.2@-785,-1007 v3(-785,-965) ; R28.2@-475,-1007 v3(-475,-965)
  Bottom Layer w13.78: -640,-970 -640,-353.11 -640,-225 -565,-150 -185,-150 -170,-135 v1(-170,-95) -170,-90 v1@-169.57,-89.57
  Bottom Layer w20: v3(-785,-965) -640,-970 v3@-475,-970
SW2_P: C29.1 L2.2 Q5.1 Q5.2 Q5.3 Q6.1 Q6.2 Q6.3 Q7.5 Q7.6 Q7.7 Q7.8 Q7.9 Q8.5 Q8.6 Q8.7 Q8.8 Q8.9 R19.2 R23.2 TP6.1 U2.18 | length 1710.3
  Top Layer w13.78: TP6.1@-400,-350 -305,-350 -130,-525 ; v1(-272,-112) C29.1@-220,-112 -220,-80 -217.03,-77.03 -200.58,-77.03 -189.02,-65.47 -143.39,-65.47 -141.9,-63.98 U2.18@-110.24,-63.98
  Bottom Layer w13.78: v1(-685,-935) -663.78,-913.78 -663.78,-215.15 -646.82,-198.19 -560.63,-112 v1(-272,-112) v1@-269,-115
  other v1: -120,-1135 -80,-1135 -40,-1135 0,-1135 185,-1135 225,-1135 265,-1135 305,-1135 -120,-1095 -80,-1095 -40,-1095 0,-1095 185,-1095 225,-1095 265,-1095 305,-1095 -120,-1055 -80,-1055 -40,-1055 0,-1055 185,-1055 225,-1055 265,-1055 305,-1055
SYN1: "Sync In 1.1" C16.2 R16.2 U1.8 | length 596.1
  Top Layer w13.78: U1.8@-1889.76,63.98 -1841.02,63.98 -1750,155 -1750,228 R16.2@-1693,285 C16.2@-1693,370
  Bottom Layer w13.78: v1(-1693,330) -1693,510
SYN2: "Sync In 2.1" C33.2 R33.2 U2.8 | length 635.3
  Top Layer w13.78: U2.8@110.24,63.98 158.98,63.98 175,80 v1(230,80) 250,60 R33.2@293.5,60 297,63.5 C33.2@297,135
  Bottom Layer w13.78: v1(230,80) 236.89,86.89 236.89,428.11 230,435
